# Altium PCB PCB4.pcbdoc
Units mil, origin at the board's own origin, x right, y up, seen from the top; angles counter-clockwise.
Board outline 779.58 x 1325.68 mil, 2 copper layers (Top Layer, Bottom Layer); 24 components, 29 nets, 107 pads, 62 vias.
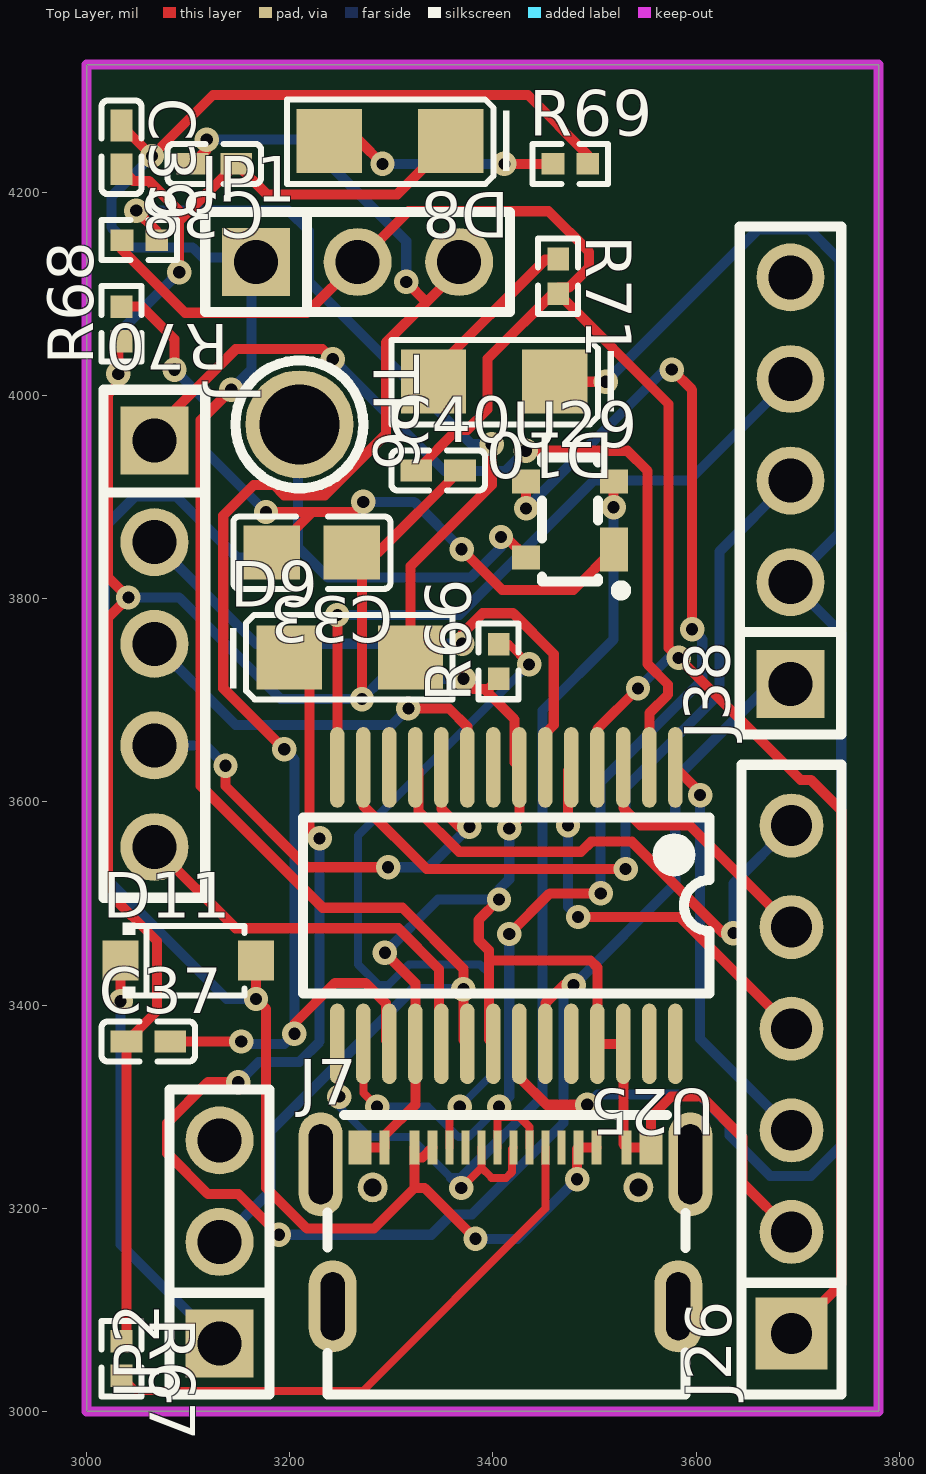
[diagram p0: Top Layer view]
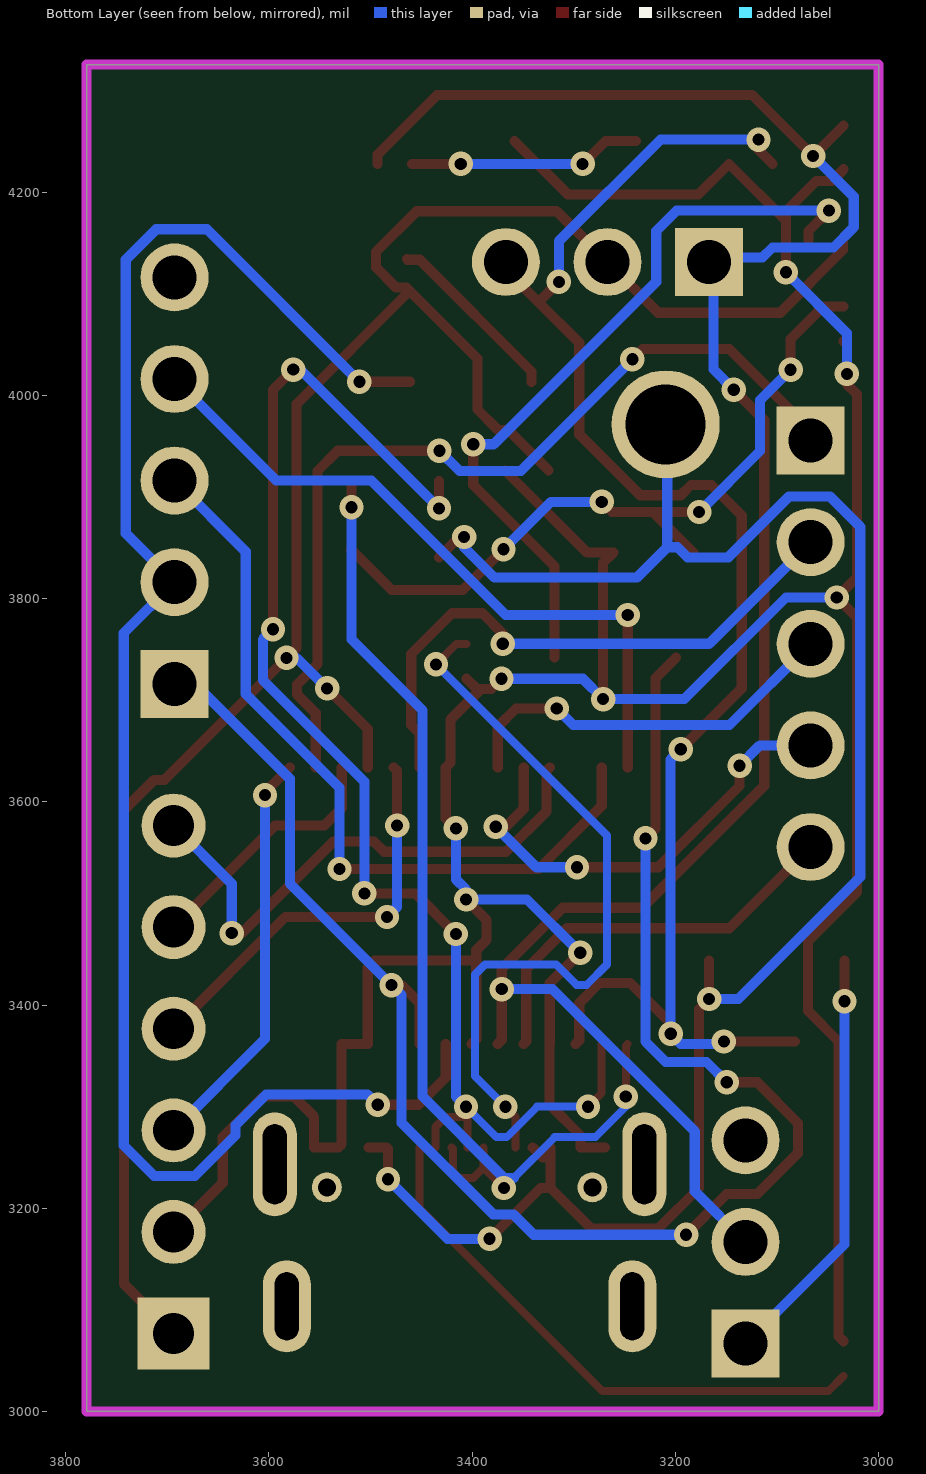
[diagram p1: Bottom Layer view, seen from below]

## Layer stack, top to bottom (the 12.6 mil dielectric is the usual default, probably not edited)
Top Layer: signal copper (thickness not stored)
Dielectric: dielectric 12.6, FR-4, Dk 4.8
Bottom Layer: signal copper (thickness not stored)

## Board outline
3000,3000 3000,4325.68 3779.58,4325.68 3779.58,3000

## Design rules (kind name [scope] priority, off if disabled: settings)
BoardOutlineClearance copperThickness1oz [All] p0: genericclearance=10 ignorepadtopadclearanceinfootprint=FALSE except(0: Arc-SplitContinuation Track-SplitContinuation SMDPad-SplitContinuation THPad-SplitContinuation Via-SplitContinuation Fill-SplitContinuation Poly-SplitContinuation Region-SplitContinuation Text-SplitContinuation; 6: Track-CutoutEdge SMDPad-CutoutEdge THPad-CutoutEdge Via-CutoutEdge Region-CutoutEdge; 11.8: Track-OutlineEdge SMDPad-OutlineEdge THPad-OutlineEdge Via-OutlineEdge Fill-OutlineEdge Region-OutlineEdge Poly-OutlineEdge Text-OutlineEdge Fill-CutoutEdge)
BoardOutlineClearance copperThickness2oz [All] p0: genericclearance=10 ignorepadtopadclearanceinfootprint=FALSE except(0: Arc-SplitContinuation Track-SplitContinuation SMDPad-SplitContinuation THPad-SplitContinuation Via-SplitContinuation Fill-SplitContinuation Poly-SplitContinuation Region-SplitContinuation Text-SplitContinuation; 6: Track-CutoutEdge SMDPad-CutoutEdge THPad-CutoutEdge Via-CutoutEdge Region-CutoutEdge; 11.8: Track-OutlineEdge SMDPad-OutlineEdge THPad-OutlineEdge Via-OutlineEdge Fill-OutlineEdge Region-OutlineEdge Poly-OutlineEdge Text-OutlineEdge Fill-CutoutEdge)
Clearance copperThickness1oz [(InNet('FT232_SHIELD1') OR InNet('GND') OR InNet('FT232_3V3OUT') OR InNet('FT232_VCC') OR InNet('FT232_VCCIO') OR InNet('$2N6177') OR InNet('$2N6473') OR InNet('CBUS0') OR InNet('$2N6471') OR InNet('CBUS1') OR InNet('FT232_VUSB') OR InNet('FT232_VUSB_PROT') OR InNet('FT232_DTR') OR InNet('FT232_RI') OR InNet('FT232_DSR') OR InNet('FT232_DCD') OR InNet('FT232_RESET') OR InNet('FT232_CC1') OR InNet('FT232_USB_D_P') OR InNet('FT232_USB_D_N') OR InNet('FT232_CC2') OR InNet('FT232_CTS') OR InNet('FT232_RTS') OR InNet('FT232_RXD') OR InNet('FT232_TXD') OR InNet('$2N3077') OR InNet('$2N3079') OR InNet('$2N3075') OR InNet('+4V5'))] p1: gap=7 ignorepadtopadclearanceinfootprint=FALSE except(4: Track-Track; 6: Track-SMDPad SMDPad-SMDPad Track-THPad SMDPad-THPad THPad-THPad Track-Via SMDPad-Via THPad-Via Via-Via SMDPad-Fill THPad-Fill Via-Fill Fill-Fill Track-Region SMDPad-Region THPad-Region Via-Region Region-Region Track-Poly SMDPad-Poly THPad-Poly Via-Poly Fill-Poly Region-Poly Poly-Poly Track-Text SMDPad-Text THPad-Text Via-Text Fill-Text Region-Text Poly-Text Text-Text; 6.9: Track-Hole SMDPad-Hole THPad-Hole Via-Hole Fill-Hole Region-Hole Poly-Hole Text-Hole Sheet-Hole; 11.8: Track-Fill Fill-Region Track-Sheet SMDPad-Sheet THPad-Sheet Via-Sheet Fill-Sheet Region-Sheet Poly-Sheet Text-Sheet)
Clearance copperThickness2oz [All] p1: gap=7 ignorepadtopadclearanceinfootprint=FALSE except(6: Track-SMDPad SMDPad-SMDPad Track-THPad SMDPad-THPad THPad-THPad Track-Via SMDPad-Via THPad-Via Via-Via SMDPad-Fill THPad-Fill Via-Fill Fill-Fill Track-Region SMDPad-Region THPad-Region Via-Region Region-Region Track-Poly SMDPad-Poly THPad-Poly Via-Poly Fill-Poly Region-Poly Poly-Poly Track-Text SMDPad-Text THPad-Text Via-Text Fill-Text Region-Text Poly-Text Text-Text; 6.9: Track-Hole SMDPad-Hole THPad-Hole Via-Hole Fill-Hole Region-Hole Poly-Hole Text-Hole Sheet-Hole; 8: Track-Track; 11.8: Track-Fill Fill-Region Track-Sheet SMDPad-Sheet THPad-Sheet Via-Sheet Fill-Sheet Region-Sheet Poly-Sheet Text-Sheet)
DiffPairsRouting differentialPair [All] p1: maxuncoupledlength=10 minlimit=6 maxlimit=6 mostfreqgap=6 toplayer_minwidth=5 toplayer_prefwidth=10 toplayer_maxwidth=100 bottomlayer_minwidth=5 bottomlayer_prefwidth=10 bottomlayer_maxwidth=100
PasteMaskExpansion pasteMaskExpansion [All] p1: expansion=0
PlaneConnect innerPlane [All] p1: planeconnectstyle=Relief reliefexpansion=20 reliefentries=4 reliefconductorwidth=10 reliefairgap=10
PolygonConnect copperRegion [All] p1: connectstyle=Relief reliefentries=4 reliefconductorwidth=10 polygonreliefangle="90 Angle" airgapwidth=10
RoutingVias viaSize [All] p1: viastyle="Through Hole" holewidth=12.0078 minholewidth=11.811 maxholewidth=248.0314 width=24.0158 minwidth=19.685 maxwidth=393.7008
SolderMaskExpansion solderMaskExpansion [All] p1: useseparateexpansions=TRUE expansion=2 expansionbottom=2
Width copperThickness1oz [All] p1: maxlimit=100 minlimit=5 preferedwidth=10
Width copperThickness2oz [All] p1: maxlimit=100 minlimit=8 preferedwidth=10

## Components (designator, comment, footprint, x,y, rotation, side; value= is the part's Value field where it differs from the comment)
C33 "FV21X472K102ECG" C0805 3221.8,3845.23 r180 top
C37 "CL05A105KP5NNNC" C0402 3060.82,3364.13 r0 top
C38 "GRM155R61H104KE19D" C0402 3125.77,4227.84 r180 top
C39 "GRM155R61H104KE19D" C0402 3034.44,4244.21 r270 top
C40 "GRM155R61H104KE19D" C0402 3346.17,3926.12 r0 top
D8 "LTST-C150KRKT" LED1206-RD 3298.6,4250.29 r180 top
D9 "LTST-C150KRKT" LED1206-RD 3259.16,3741.9 r0 top
D10 "LTST-C150KRKT" LED1206-RD 3401.29,4013.52 r180 top
D11 "PMEG6020AELRX" SOD-123_L2.6-W1.7-LS3.5-RD 3100.17,3443.64 r0 top
J "PZ254V-11-05P" HDR-TH_5P-P2.54-V-M 3066.81,3755.53 r270 top
J7 "CX90B-16P" USB-C-SMD_CX90B-16P 3412.42,3181.66 r0 top
J26 "2.54-1*6P母" HDR-TH_6P-P2.54-V-F 3693.87,3326.65 r90 top
J38 "PZ254V-11-05P" HDR-TH_5P-P2.54-V-M 3692.91,3916.19 r90 top
JP1 "PZ254V-11-03P" HDR-TH_3P-P2.54-V-M 3266.85,4131.31 r0 top
JP2 "PZ254V-11-03P" HDR-TH_3P-P2.54-V-M 3130.97,3166.81 r90 top
R66 "RC0402FR-075K1L" R0402 3405.61,3738.17 r90 top
R67 "RC0402FR-075K1L" R0402 3034.44,3051.99 r270 top
R68 "CRCW04021M00FKED" R0402 3034.44,4070.39 r90 top
R69 "RC0402FR-075K1L" R0402 3476.12,4227.84 r0 top
R70 "RC0402FR-075K1L" R0402 3051.99,4152.88 r180 top
R71 "RC0402FR-075K1L" R0402 3464.16,4117.28 r270 top
TP6 "FT232_VUBS_CONN" TESTPOINT-TH_BD3.2 3209.49,3971.48 r270 top
U25 "FT232RL-REEL" SSOP-28_L10.2-W5.3-P0.65-LS7.8-BL 3413.22,3497.8 r180 top
U29 "PRTR5V0U2X-ES" SOT-143_L2.9-W1.3-P1.92-LS2.3-BR 3475.97,3878.04 r0 top

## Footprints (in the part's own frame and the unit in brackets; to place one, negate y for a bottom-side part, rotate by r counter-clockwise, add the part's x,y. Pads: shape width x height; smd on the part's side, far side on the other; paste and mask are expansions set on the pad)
C0402 [mm]
  rect 0.79x0.54 smd: 1(-0.545,0) 2(0.545,0)
  silkscreen extent -1.17,-0.5 1.17,0.5
C0805 [mm]
  rect 1.41x1.35 smd: 1(-1,0) 2(1,0)
  silkscreen extent -1.96,-0.9 1.96,0.9
HDR-TH_3P-P2.54-V-M [mm]
  rect 1.7x1.7 hole 1.1: 1(-2.54,0)
  round 1.7 hole 1.1: 2(0,0) 3(2.54,0)
  silkscreen extent -3.81,-1.25 3.81,1.25
HDR-TH_5P-P2.54-V-M [mm]
  rect 1.7x1.7 hole 1.1: 1(-5.08,0)
  round 1.7 hole 1.1: 2(-2.54,0) 3(0,0) 4(2.54,0) 5(5.08,0)
  silkscreen extent -6.35,-1.27 6.35,1.27
HDR-TH_6P-P2.54-V-F [mm]
  rect 1.8x1.8 hole 1.02: 1(-6.35,0)
  round 1.6 hole 1.02: 2(-3.81,0) 3(-1.27,0) 4(1.27,0) 5(3.81,0) 6(6.35,0)
  silkscreen extent -7.87,-1.25 7.87,1.25
LED1206-RD [mm]
  rect 1.635x1.6 smd: 1(-1.517,0) 2(1.517,0)
  silkscreen extent -2.99,-1.04 2.57,1.07
R0402 [mm]
  rect 0.566x0.54 smd: 1(-0.433,0) 2(0.433,0)
  silkscreen extent -0.94,-0.5 0.94,0.5
SOD-123_L2.6-W1.7-LS3.5-RD [mm]
  rect 0.9x1 smd: 1(-1.692,0) 2(1.692,0)
  silkscreen extent -1.63,-0.94 1.41,0.94
SOT-143_L2.9-W1.3-P1.92-LS2.3-BR [mm]
  rect 0.7x1.1 smd: 1(1.1,-0.75)
  rect 0.7x0.6 smd: 2(1.1,0.95) 3(-1.1,0.95) 4(-1.1,-0.95)
  silkscreen extent -0.7,-1.91 1.4,1.55
SSOP-28_L10.2-W5.3-P0.65-LS7.8-BL [mil]
  oval 14.33x79.35 smd: 1(-166.34,-136.03) 2(-140.75,-136.03) 3(-115.16,-136.03) 4(-89.57,-136.03) 5(-63.98,-136.03) 6(-38.39,-136.03) 7(-12.79,-136.03) 8(12.8,-136.03) 9(38.39,-136.03) 10(63.98,-136.03) 11(89.57,-136.03) 12(115.16,-136.03) 13(140.75,-136.03) 14(166.34,-136.03) 15(166.34,136.03) 16(140.75,136.03) 17(115.16,136.03) 18(89.57,136.03) 19(63.98,136.03) 20(38.39,136.03) 21(12.8,136.03) 22(-12.79,136.03) 23(-38.39,136.03) 24(-63.98,136.03) 25(-89.57,136.03) 26(-115.16,136.03) 27(-140.75,136.03) 28(-166.34,136.03)
  silkscreen extent -200,-87 200,87
TESTPOINT-TH_BD3.2 [mm]
  round 2.7 hole 2: 1(0,0)
  silkscreen extent -1.6,-1.6 1.6,1.6
USB-C-SMD_CX90B-16P [mm]
  oval 1.1x2.6 hole 0.6 slot 2 at 90 deg: 0(-4.62,1.563) 0(4.62,1.563)
  oval 1.2x2.3 hole 0.6 slot 1.7 at 90 deg: 1(-4.32,-1.987) 1(4.32,-1.987)
  round 0.75 hole 0.45: 2(-3.32,0.988) 3(3.32,0.988)
  rect 0.57x0.85 smd: A1(-3.635,1.987) A12(3.635,1.987)
  rect 0.25x0.85 smd: A4(-2.275,1.987) A9(2.275,1.987) B1(3.025,1.987) B4(1.825,1.987) B9(-1.825,1.987) B12(-3.025,1.987)
  rect 0.2x0.85 smd: A5(-1.4,1.987) A6(-0.6,1.987) A7(0.6,1.987) A8(1.4,1.987) B5(1,1.987) B6(0.2,1.987) B7(-0.2,1.987) B8(-1,1.987)
  silkscreen extent -4.45,-4.19 4.5,2.8

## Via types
v1: diameter 24.02, hole 12.01, Top Layer to Bottom Layer, 62 vias

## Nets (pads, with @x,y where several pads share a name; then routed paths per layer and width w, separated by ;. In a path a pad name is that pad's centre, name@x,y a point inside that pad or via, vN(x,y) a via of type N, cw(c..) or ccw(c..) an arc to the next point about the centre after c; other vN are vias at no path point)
$2N3075: J38.5 U25.12
$2N3077: J38.3 U25.13 | length 771.2
  Top Layer w10: U25.13 3272.47,3596.14 3334.78,3533.83 v1(3530.55,3533.83)
  Bottom Layer w10: v1(3530.55,3533.83) 3530.55,3613.83 3622.91,3706.19 3622.91,3846.19 J38.3
$2N3079: J38.4 U25.14 | length 692.3
  Top Layer w10: U25.14 v1(3246.88,3783.83)
  Bottom Layer w10: v1(3246.88,3783.83) 3366.88,3783.83 3499.24,3916.19 3592.91,3916.19 J38.4
$2N6177: D8.2 R69.1 | length 229.5
  Top Layer w10: D8.2 3268.86,4250.29 v1(3291.31,4227.84) ; v1(3411.31,4227.84) R69.1
  Bottom Layer w10: v1(3291.31,4227.84) v1(3411.31,4227.84)
$2N6471: D10.2 R71.1 | length 178.5
  Top Layer w10: D10.2 3341.55,4023.52 3451.55,4133.52 3463.36,4133.52 R71.1
$2N6473: D9.2 R70.1 | length 755
  Top Layer w10: v1(3048.9,4181.9) 3069.03,4161.77 R70.1 ; D9.2 3318.9,3831.9 3398.9,3911.9 v1(3398.9,3951.9)
  Bottom Layer w10: v1(3048.9,4181.9) 3198.9,4181.9 3218.9,4161.9 3218.9,4111.9 3378.9,3951.9 v1(3398.9,3951.9)
+4V5: JP2.3
CBUS0: D9.1 J38.1 U25.23 | length 1683.9
  Top Layer w10: v1(3149.42,3323.96) 3119.42,3323.96 3079.42,3283.96 3079.42,3253.96 3119.42,3213.96 3149.42,3213.96 v1(3189.42,3173.96) ; D9.1 3219.42,3721.9 3219.42,3573.96 v1(3229.42,3563.96) ; U25.23 3451.61,3401.77 3469.42,3419.58 v1(3479.42,3419.58)
  Bottom Layer w10: v1(3149.42,3323.96) 3169.42,3343.96 3209.42,3343.96 3229.42,3363.96 v1(3229.42,3563.96) ; v1(3189.42,3173.96) 3339.42,3173.96 3359.42,3193.96 3379.42,3193.96 3469.42,3283.96 3469.42,3409.58 v1(3479.42,3419.58) 3579.42,3519.58 3579.42,3622.7 3672.91,3716.19 J38.1
CBUS1: D10.1 J38.2 U25.22 | length 1683.7
  Top Layer w10: U25.22 3426.01,3328.66 3452.91,3301.77 v1(3492.91,3301.77) ; D10.1 v1(3511.03,4013.52)
  Bottom Layer w10: v1(3492.91,3301.77) 3502.91,3311.77 3602.91,3311.77 3632.91,3281.77 3632.91,3271.77 3672.91,3231.77 3712.91,3231.77 3742.91,3261.77 3742.91,3766.19 J38.2 3741.03,3864.31 3741.03,4133.52 3711.03,4163.52 3661.03,4163.52 v1(3511.03,4013.52)
FT232_3V3OUT: C37.2 C38.2 JP1.3 U25.17 | length 1569.4
  Top Layer w10: C37.2 v1(3152.28,3364.13) ; C38.2 3118.24,4241.77 v1(3118.24,4251.77) ; v1(3194.64,3651.77) 3134.64,3711.77 3134.64,3881.77 3164.64,3911.77 3184.64,3911.77 3194.64,3901.77 3234.64,3901.77 3294.64,3961.77 3294.64,4051.77 3334.64,4091.77 ; v1(3204.64,3371.77) 3204.64,3381.77 3244.64,3421.77 3274.64,3421.77 3294.64,3401.77 3294.64,3365.19 U25.17 ; v1(3314.64,4111.77) 3334.64,4091.77 ; JP1.3 3366.85,4123.97 3334.64,4091.77
  Bottom Layer w10: v1(3118.24,4251.77) 3214.64,4251.77 3314.64,4151.77 v1(3314.64,4111.77) ; v1(3152.28,3364.13) 3154.64,3361.77 3194.64,3361.77 v1(3204.64,3371.77) 3204.64,3641.77 v1(3194.64,3651.77)
FT232_CC1: J7.A5 R66.2 | length 740.6
  Top Layer w7.87: J7.A5 3357.31,3289.91 v1(3367.31,3299.91) ; R66.2 3415.61,3755.21 v1(3435.61,3735.21)
  Bottom Layer w7.87: v1(3367.31,3299.91) 3397.31,3329.91 3397.31,3429.91 3387.31,3439.91 3317.31,3439.91 3297.31,3419.91 3287.31,3419.91 3267.31,3439.91 3267.31,3566.91 v1(3435.61,3735.21)
FT232_CC2: J7.B5 R67.2 | length 558.1
  Top Layer w7.87: R67.2 3049.48,3019.91 3271.8,3019.91 3451.8,3199.91 J7.B5
FT232_CTS: J26.6 U25.11 | length 541.9
  Top Layer w10: U25.11 3326.7,3630.78 3326.7,3590.78 3366.7,3550.78 3486.7,3550.78 3496.7,3560.78 3536.7,3560.78 3626.7,3470.78 v1(3636.7,3470.78)
  Bottom Layer w10: v1(3636.7,3470.78) 3636.7,3519.48 J26.6
FT232_DCD: J.4 U25.10 | length 463.6
  Top Layer w10: v1(3136.81,3635.53) 3136.81,3615.53 3216.81,3535.53 v1(3296.81,3535.53) ; U25.10 3349.24,3593.1 3366.81,3575.53 v1(3376.81,3575.53)
  Bottom Layer w10: J.4 3116.81,3655.53 v1(3136.81,3635.53) ; v1(3296.81,3535.53) 3336.81,3535.53 v1(3376.81,3575.53)
FT232_DSR: J.3 U25.9 | length 395.4
  Top Layer w10: v1(3316.81,3691.85) 3356.81,3691.85 3374.83,3673.83 U25.9
  Bottom Layer w10: J.3 3146.81,3675.53 3300.5,3675.53 v1(3316.81,3691.85)
FT232_DTR: J.1 U25.2 | length 902.4
  Top Layer w10: J.1 3066.81,3965.53 3146.81,4045.53 3232.27,4045.53 v1(3242.27,4035.53) ; v1(3432.27,3945.53) 3532.27,3945.53 3552.27,3925.53 3552.27,3735.53 3572.27,3715.53 3572.27,3705.53 3553.97,3687.24 U25.2
  Bottom Layer w10: v1(3242.27,4035.53) 3352.27,3925.53 3412.27,3925.53 v1(3432.27,3945.53)
FT232_RESET: J.5 U25.19 | length 404.5
  Top Layer w10: J.5 3146.81,3475.53 3306.81,3475.53 3346.81,3435.53 3346.81,3364.2 U25.19
FT232_RI: J.2 U25.6 | length 584.5
  Top Layer w10: v1(3369.91,3755.53) 3369.91,3765.53 3389.91,3785.53 3419.91,3785.53 3459.91,3745.53 3459.91,3675.53 3451.61,3667.24 U25.6
  Bottom Layer w10: J.2 3166.81,3755.53 v1(3369.91,3755.53)
FT232_RTS: J26.5 U25.3 | length 254
  Top Layer w10: U25.3 3528.38,3593.83 3545.55,3576.65 3593.87,3576.65 J26.5
FT232_RXD: J26.4 U25.5 | length 408.3
  Top Layer w10: v1(3473.87,3576.65) 3473.87,3630.5 U25.5 ; v1(3483.87,3486.65) 3583.87,3486.65 J26.4
  Bottom Layer w10: v1(3473.87,3576.65) 3473.87,3496.65 v1(3483.87,3486.65)
FT232_SHIELD1: C33.2 R68.2 U29.1 | length 728.7
  Top Layer w10: R68.2 3054.44,4087.43 3086.64,4055.23 v1(3086.64,4025.23) ; v1(3176.64,3885.23) 3222.43,3885.23 ; C33.2 3222.43,3885.23 ; v1(3272.43,3895.23) 3262.43,3885.23 3222.43,3885.23 ; v1(3369.15,3848.51) 3409.15,3808.51 3479.27,3808.51 U29.1
  Bottom Layer w10: v1(3086.64,4025.23) 3116.64,3995.23 3116.64,3945.23 v1(3176.64,3885.23) ; v1(3272.43,3895.23) 3322.43,3895.23 v1(3369.15,3848.51)
FT232_TXD: J26.3 U25.1 | length 404.5
  Top Layer w10: U25.1 3603.87,3609.52 v1(3603.87,3606.65)
  Bottom Layer w10: v1(3603.87,3606.65) 3603.87,3366.65 J26.3
FT232_USB_D_N: J7.A7 J7.B7 U25.16 U29.3 | length 1383.8
  Top Layer w7.87: U25.16 3272.47,3313.48 v1(3286.05,3299.91) ; J7.B7 3404.55,3288.41 v1@3406.05,3289.91 ; v1(3406.05,3299.91) v1@3406.05,3289.91 ; J7.A7 3436.05,3279.91 3426.05,3289.91 v1@3406.05,3289.91
  Top Layer w10: v1(3416.05,3469.91) 3456.05,3509.91 v1(3506.05,3509.91) ; v1(3432.66,3888.82) U29.3 ; v1(3576.05,4025.44) 3596.05,4005.44 v1(3596.05,3769.91)
  Bottom Layer w7.87: v1(3286.05,3299.91) 3336.05,3299.91 3366.05,3269.91 3376.05,3269.91 v1(3406.05,3299.91)
  Bottom Layer w10: v1(3406.05,3299.91) 3416.05,3309.91 v1(3416.05,3469.91) ; v1(3432.66,3888.82) 3569.28,4025.44 v1(3576.05,4025.44) ; v1(3506.05,3509.91) 3506.05,3619.91 3606.05,3719.91 3606.05,3759.91 v1(3596.05,3769.91)
FT232_USB_D_P: J7.A6 J7.B6 U25.15 U29.2 | length 1083.3
  Top Layer w7.87: U25.15 3248.8,3359.85 v1(3248.8,3309.91) ; v1(3368.8,3219.91) 3388.8,3239.91 ; J7.A6 3388.8,3239.91 ; J7.B6 3418.8,3258.41 3418.8,3235.68 3413.03,3229.91 3398.8,3229.91 3388.8,3239.91
  Top Layer w10: v1(3518.8,3889.91) 3518.8,3914.96 U29.2
  Bottom Layer w7.87: v1(3248.8,3309.91) 3248.8,3299.91 3278.8,3269.91 3318.8,3269.91 3358.8,3229.91 v1(3368.8,3219.91)
  Bottom Layer w10: 3358.8,3229.91 3368.8,3229.91 3448.8,3309.91 3448.8,3689.91 3518.8,3759.91 v1(3518.8,3889.91)
FT232_VCC: C39.1 JP1.1 JP2.2 R69.2 U25.20 | length 2099.4
  Top Layer w10: C39.1 v1(3064.44,4235.67) 3124.44,4295.67 3434.44,4295.67 3493.16,4236.95 R69.2 ; v1(3142.49,4005.67) 3112.49,3975.67 3112.49,3615.67 3232.49,3495.67 3310.93,3495.67 3370.93,3435.67 v1(3370.93,3415.67) 3370.93,3365.67 U25.20
  Bottom Layer w10: v1(3064.44,4235.67) 3024.44,4195.67 3024.44,4165.67 3044.44,4145.67 3104.44,4145.67 3114.44,4135.67 JP1.1@3162.49,4135.67 ; JP2.2 3180.93,3216.77 3180.93,3275.67 3320.93,3415.67 v1(3370.93,3415.67) ; v1(3142.49,4005.67) 3162.49,4025.67 JP1.1@3162.49,4135.67 ; JP1.1 JP1.1@3162.49,4135.67
FT232_VCCIO: C40.1 J26.1 JP1.2 R70.2 R71.2 U25.4 | length 2168.2
  Top Layer w10: R70.2 3034.95,4143.21 3096.85,4081.31 3216.85,4081.31 JP1.2 3316.85,4181.31 3454.71,4181.31 3494.71,4141.31 3494.71,4126.12 3474.71,4106.12 R71.2@3464.71,4106.12 ; C40.1 3364.71,3966.12 3374.71,3966.12 3394.71,3986.12 3394.71,4036.12 R71.2@3464.71,4106.12 ; U25.4 3502.79,3671.61 v1(3542.79,3711.61) ; J26.1 3742.79,3125.57 3742.79,3591.61 3712.79,3621.61 3702.79,3621.61 v1(3582.79,3741.61) 3572.79,3751.61 3572.79,3991.61 R71.2 R71.2@3464.71,4106.12
  Bottom Layer w10: v1(3542.79,3711.61) 3572.79,3741.61 v1(3582.79,3741.61)
FT232_VUSB: D11.2 J7.A4 J7.A9 J7.B4 J7.B9 TP6.1 U29.4 | length 1887.5
  Top Layer w9.84: D11.2 v1(3166.8,3405.96) 3176.8,3395.96 3176.8,3219.91 3216.8,3179.91 3282.86,3179.91 3322.86,3219.91 ; J7.A4 J7.A4@3322.86,3249.91 ; J7.B9 3330.58,3249.91 J7.A4@3322.86,3249.91 ; v1(3382.86,3169.91) 3332.86,3219.91 3322.86,3219.91 ; v1(3482.86,3228.5) 3482.86,3258.5 J7.B4 J7.A9 ; 3322.86,3219.91 J7.A4@3322.86,3249.91
  Top Layer w10: v1(3407.99,3860.63) 3412.66,3860.63 U29.4
  Bottom Layer w9.84: v1(3382.86,3169.91) 3424.27,3169.91 v1(3482.86,3228.5)
  Bottom Layer w10: v1(3166.8,3405.96) 3137.99,3405.96 3017.99,3525.96 3017.99,3870.63 3047.99,3900.63 3087.99,3900.63 3147.99,3840.63 3187.99,3840.63 3197.99,3850.63 3207.99,3850.63 ; TP6.1 3207.99,3969.99 3207.99,3850.63 ; v1(3407.99,3860.63) 3407.99,3850.63 3377.99,3820.63 3237.99,3820.63 3207.99,3850.63
FT232_VUSB_PROT: D11.1 JP2.1 | length 417.2
  Top Layer w10: v1(3033.54,3403.64) D11.1
  Bottom Layer w10: v1(3033.54,3403.64) 3033.54,3164.24 JP2.1
GND: C33.1 C37.1 C38.1 C39.2 C40.2 D8.1 J7.A1 J7.A12 J7.B1 J7.B12 J26.2 R66.1 R67.1 R68.1 U25.7 U25.18 U25.21 U25.25 U25.26 | length 3691.5
  Top Layer w9.84: J7.A1 J7.B12 3293.33,3271.44 3323.65,3301.77 U25.18 ; U25.26 3528.38,3263.04 J7.B1 J7.A12
  Top Layer w10: R67.1 3039.36,3073.95 C37.1 3069.36,3394.13 3069.36,3462.94 3021.17,3511.13 3021.17,3781.13 v1(3041.17,3801.13) 3021.17,3821.13 3021.17,4001.13 3031.17,4011.13 3031.17,4050.09 R68.1 ; C39.2 3046.06,4211.13 3061.17,4211.13 3091.17,4181.13 3091.17,4171.79 ; v1(3091.17,4121.13) 3091.17,4171.79 ; v1(3271.17,3701.13) 3271.17,3835.23 C33.1 3286.74,3845.23 C40.2 ; v1(3293.65,3451.47) 3323.65,3421.47 U25.18 ; D8.1 3305.89,4197.84 3177.23,4197.84 C38.1 3091.17,4171.79 ; v1(3371.17,3721.13) 3381.17,3711.13 3391.17,3711.13 ; U25.21 3396.01,3366.18 3396.01,3443.83 ; R66.1 3395.61,3711.13 3391.17,3711.13 ; v1(3406.01,3503.83) 3386.01,3483.83 3386.01,3463.83 3396.01,3453.83 3396.01,3443.83 ; v1(3416.01,3573.83) 3426.01,3583.83 U25.7 3421.17,3638.67 3421.17,3681.13 3391.17,3711.13 ; U25.26 U25.25 3502.79,3437.05 3496.01,3443.83 3396.01,3443.83 ; J7.A12 3555.54,3289.91 3575.54,3309.91 3605.54,3309.91 3645.54,3269.91 3645.54,3224.99 J26.2
  Bottom Layer w10: v1(3031.17,4021.13) 3031.17,4061.13 v1(3091.17,4121.13) ; v1(3041.17,3801.13) 3091.17,3801.13 3191.17,3701.13 v1(3271.17,3701.13) 3291.17,3721.13 v1(3371.17,3721.13) ; v1(3293.65,3451.47) 3346.01,3503.83 v1(3406.01,3503.83) 3406.01,3513.83 3416.01,3523.83 v1(3416.01,3573.83)
pads on no net: J7.0 J7.1 J7.2 J7.3 J7.A8 J7.B8 U25.8 U25.24 U25.27 U25.28

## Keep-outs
Board Outline Layer:
  the board outline again, w10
